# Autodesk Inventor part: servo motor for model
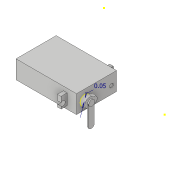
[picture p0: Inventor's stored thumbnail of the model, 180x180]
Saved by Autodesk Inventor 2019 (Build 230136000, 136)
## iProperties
Created: 2020-02
Part Number: servo motor for model
Material: Generic
Document SubType Name: Modeling
Designer: Krupashree
Density: 1 g/cm^3
Appearance: Default
Author: Krupashree
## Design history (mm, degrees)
sketch "Sketch1"
  geometry: L1 (10.273, 14.569)-(7.273, 14.569); L2 (10.273, 14.569)-(10.273, 7.927); L3 (10.273, 7.927)-(7.273, 7.927); L4 (7.273, 7.927)-(7.273, 14.569); 1 further point
  constraints: 8 end point, 1 horizontal, 1 perpendicular
  dimensions: "d0" = 3 distance of L1.start L1.end
extrude "Extrusion1" new body sketch "Sketch1" distance "d1" = 10; taper "d2" = 0 deg
sketch "Sketch2"
  geometry: L1 (-8.452, 0.525)-(-7.845, 0.525); L2 (-7.845, 0.525)-(-7.845, 2.346); L3 (-7.845, 2.346)-(-8.452, 2.346); L4 (-8.452, 2.346)-(-8.452, 0.525); 1 further point
  constraints: 8 end point, 2 parallel, 1 horizontal, 1 perpendicular
extrude "Extrusion2" join sketch "Sketch2" distance "d3" = 1; taper "d4" = 0 deg
sketch "Sketch3"
  geometry: L1 (8.452, 2.346)-(7.845, 2.346) reference; L2 (7.845, 0.525)-(8.452, 0.525) reference; L3 (8.452, 2.346)-(7.845, 2.346); L4 (7.845, 2.346)-(7.845, 0.525); L5 (7.845, 0.525)-(8.452, 0.525); L6 (8.452, 0.525)-(8.452, 2.346); 1 further point
  constraints: 8 end point, 2 parallel, 1 horizontal, 1 perpendicular
extrude "Extrusion3" join sketch "Sketch3" distance "d5" = 1; taper "d6" = 0 deg
sketch "Sketch4"
  geometry: A1 r 0.783 centre (-13.215, 8.732) between (-12.592, 9.206) and (-12.592, 8.258); A2 r 0.5 centre (-12.432, 8.732) between (-12.592, 8.258) and (-12.592, 9.206); 1 further point
  constraints: 5 point on circle, 2 centre point
  dimensions: "d7" = 1 diameter of A2
extrude "Extrusion4" join sketch "Sketch4" distance "d8" = 0.8; taper "d9" = 0 deg
sketch "Sketch5"
  geometry: C1 r 0.25 at (-13.215, 8.732); A1 r 0.783 centre (-13.215, 8.732) between (-12.592, 9.206) and (-12.592, 8.258) reference; 1 further point
  constraints: 1 centre point, 1 coincident
  dimensions: "d10" = 0.5 diameter of C1
workplane "Work Plane1"
sketch "Sketch6"
  geometry: C1 r 0.5 at (-13.028, 8.685); 1 further point
  constraints: 1 centre point
  dimensions: "d12" = 1 diameter of C1
extrude "Extrusion5" join sketch "Sketch6" distance "d13" = 0.2; taper "d14" = 0 deg
workplane "Work Plane2"
sketch "Sketch7"
  geometry: C1 r 0.322 at (-8.789, 8.553); 1 further point
  constraints: 1 centre point
extrude "Extrusion6" cut sketch "Sketch7" stored distance "d16" = 0.2; taper "d17" = 0 deg
workplane "Work Plane3"
workplane "Work Plane4"
sketch "Sketch8"
  geometry: C1 r 0.39 at (-0.701, 0.66); 1 further point
  constraints: 1 centre point
extrude "Extrusion7" cut sketch "Sketch8" extent not by distance; stored distance "d20" = 0.2; taper "d21" = 0 deg
sketch "Sketch9"
  geometry: C1 r 0.381 at (0.696, 0.974); 1 further point
  constraints: 1 centre point
extrude "Extrusion8" cut sketch "Sketch9" extent not by distance; stored distance "d22" = 0; taper "d23" = 0 deg
workplane "Work Plane5"
sketch "Sketch10"
  geometry: C1 r 0.25 at (10.727, 9.01); 1 further point
  constraints: 1 centre point
  dimensions: "d25" = 0.5 diameter of C1
extrude "Extrusion9" join sketch "Sketch10" distance "d26" = 0.1; taper "d27" = 0 deg
sketch "Sketch11"
  geometry: 1 further point
workplane "Work Plane6"
sketch "Sketch12"
  geometry: L1 (-12.528, 8.685)-(-12.528, 5.478); L2 (-13.528, 8.685)-(-13.528, 5.478); A1 r 0.5 centre (-13.028, 8.685) between (-12.528, 8.685) and (-13.528, 8.685) reference; A2 r 0.5 centre (-13.028, 5.478) between (-13.528, 5.478) and (-12.528, 5.478); 1 further point
  constraints: 4 end point, 4 point on circle, 3 tangent, 2 vertical, 1 centre point
extrude "Extrusion10" join sketch "Sketch12" distance "d29" = 0.11; taper "d30" = 0 deg
sketch "Sketch13"
  geometry: C1 r 0.25 at (5.058, 2.943); 1 further point
  constraints: 1 centre point
  dimensions: "d31" = 0.5 diameter of C1
extrude "Extrusion11" join sketch "Sketch13" distance "d32" = 0.3; taper "d33" = 0 deg
body "Solid1"
other parameters: "d11" = 0, "d15" = 0, "d18" = 0, "d19" = 0, "d24" = 0, "d28" = 0
